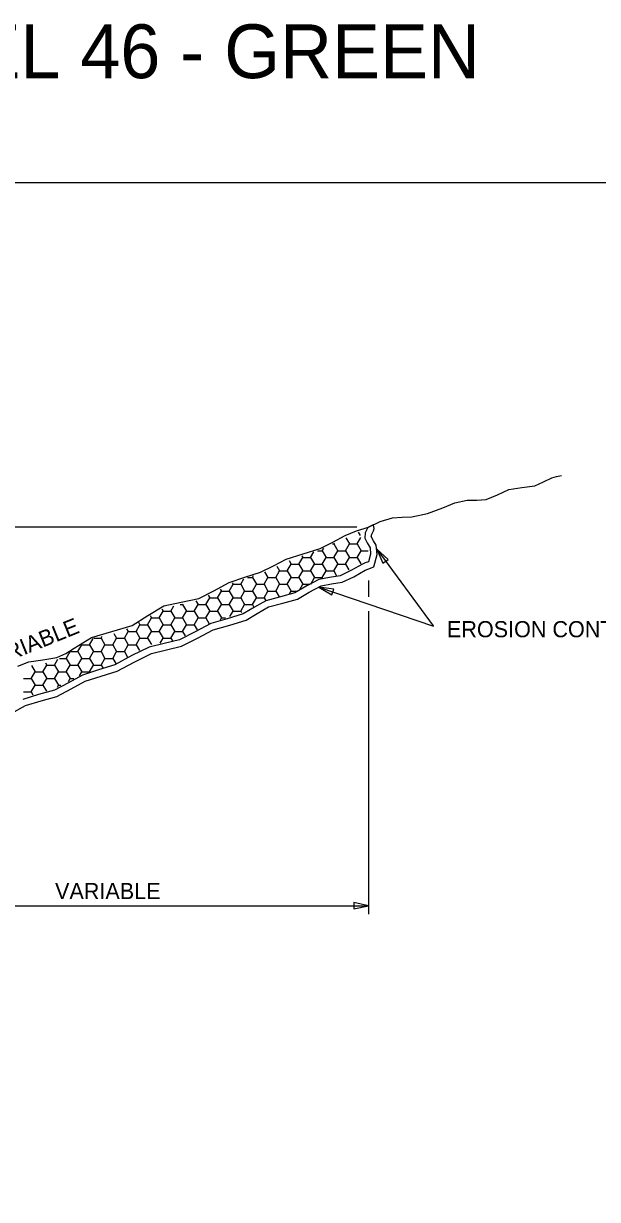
# Model space of a CAD drawing. Extents: x -439.1 to -407.9, y -458.1 to -436.2.
# Drawn here: x -424.75 to -419.41, y -447.12 to -436.2 of the extents above; entities that cross this region are included whole.
import ezdxf

# ---------------------------------------------------------------- set-up
doc = ezdxf.new("R2010")
doc.units = 0
for name, color, linetype in [('Default', 7, 'Continuous'), ('Draft_Named_Boundary', 7, 'Continuous'), ('Level 46', 7, 'Continuous')]:
    doc.layers.add(name, color=color, linetype=linetype)

msp = doc.modelspace()

# ---------------------------------------------------------------- linework, layer by layer
at = {"layer": 'Default'}
for p, q in [((-421.646, -440.877), (-427.407, -440.877)), ((-421.537, -440.877), (-421.544, -440.879)), ((-421.493, -440.855), (-421.537, -440.877)), ((-421.749, -440.976), (-421.715, -441.033)), ((-421.643, -441.033), (-421.608, -440.973)), ((-421.635, -440.923), (-421.616, -440.955)), ((-422.076, -441.158), (-422.047, -441.107)), ((-422.012, -441.096), (-421.968, -441.096)), ((-421.968, -441.096), (-421.954, -441.071)), ((-421.968, -441.096), (-421.932, -441.158)), ((-421.873, -441.033), (-421.86, -441.033)), ((-421.86, -441.033), (-421.855, -441.025)), ((-421.86, -441.033), (-421.824, -441.096)), ((-421.86, -441.158), (-421.824, -441.096)), ((-421.824, -441.096), (-421.752, -441.096)), ((-421.752, -441.096), (-421.715, -441.033)), ((-421.752, -441.096), (-421.715, -441.158)), ((-421.715, -441.033), (-421.643, -441.033)), ((-421.643, -441.033), (-421.607, -441.096)), ((-421.643, -441.158), (-421.607, -441.096)), ((-421.607, -441.096), (-421.541, -441.096)), ((-421.461, -441.081), (-420.937, -441.794)), ((-422.293, -441.283), (-422.257, -441.221)), ((-422.277, -441.186), (-422.257, -441.221)), ((-422.257, -441.221), (-422.185, -441.221)), ((-422.185, -441.221), (-422.148, -441.158)), ((-422.185, -441.221), (-422.148, -441.283)), ((-422.157, -441.144), (-422.148, -441.158)), ((-422.148, -441.158), (-422.076, -441.158)), ((-422.076, -441.158), (-422.04, -441.221)), ((-422.076, -441.283), (-422.04, -441.221)), ((-422.04, -441.221), (-421.968, -441.221)), ((-421.968, -441.221), (-421.932, -441.158)), ((-421.968, -441.221), (-421.932, -441.283)), ((-421.932, -441.158), (-421.86, -441.158)), ((-421.86, -441.158), (-421.824, -441.221)), ((-421.86, -441.283), (-421.824, -441.221)), ((-421.824, -441.221), (-421.752, -441.221)), ((-421.752, -441.221), (-421.715, -441.158)), ((-421.752, -441.221), (-421.72, -441.275)), ((-421.715, -441.158), (-421.643, -441.158)), ((-421.643, -441.158), (-421.608, -441.219)), ((-422.618, -441.346), (-422.606, -441.326)), ((-422.504, -441.292), (-422.473, -441.346)), ((-422.401, -441.346), (-422.365, -441.283)), ((-422.39, -441.24), (-422.365, -441.283)), ((-422.365, -441.283), (-422.293, -441.283)), ((-422.293, -441.283), (-422.257, -441.346)), ((-422.185, -441.346), (-422.148, -441.283)), ((-422.148, -441.283), (-422.076, -441.283)), ((-422.076, -441.283), (-422.04, -441.346)), ((-421.968, -441.346), (-421.932, -441.283)), ((-421.932, -441.283), (-421.86, -441.283)), ((-421.86, -441.283), (-421.834, -441.328)), ((-422.834, -441.471), (-422.798, -441.408)), ((-422.806, -441.394), (-422.798, -441.408)), ((-422.798, -441.408), (-422.726, -441.408)), ((-422.726, -441.408), (-422.696, -441.356)), ((-422.726, -441.408), (-422.69, -441.471)), ((-422.664, -441.346), (-422.618, -441.346)), ((-422.618, -441.346), (-422.581, -441.408)), ((-422.618, -441.471), (-422.581, -441.408)), ((-422.581, -441.408), (-422.509, -441.408)), ((-422.509, -441.408), (-422.473, -441.346)), ((-422.509, -441.408), (-422.473, -441.471)), ((-422.473, -441.346), (-422.401, -441.346)), ((-422.401, -441.346), (-422.365, -441.408)), ((-422.401, -441.471), (-422.365, -441.408)), ((-422.365, -441.408), (-422.293, -441.408)), ((-422.293, -441.408), (-422.257, -441.346)), ((-422.293, -441.408), (-422.257, -441.471)), ((-422.257, -441.346), (-422.185, -441.346)), ((-422.185, -441.346), (-422.148, -441.408)), ((-422.177, -441.457), (-422.148, -441.408)), ((-422.148, -441.408), (-422.08, -441.408)), ((-422.075, -441.406), (-422.04, -441.346)), ((-422.04, -441.346), (-421.968, -441.346)), ((-422.001, -441.435), (-420.932, -441.798)), ((-421.968, -441.346), (-421.965, -441.35)), ((-421.537, -441.373), (-421.537, -441.524)), ((-423.051, -441.596), (-423.015, -441.533)), ((-423.028, -441.509), (-423.015, -441.533)), ((-423.015, -441.533), (-422.942, -441.533)), ((-422.942, -441.533), (-422.906, -441.471)), ((-422.942, -441.533), (-422.906, -441.596)), ((-422.917, -441.452), (-422.906, -441.471)), ((-422.906, -441.471), (-422.834, -441.471)), ((-422.834, -441.471), (-422.798, -441.533)), ((-422.834, -441.596), (-422.798, -441.533)), ((-422.798, -441.533), (-422.726, -441.533)), ((-422.726, -441.533), (-422.69, -441.471)), ((-422.726, -441.533), (-422.69, -441.596)), ((-422.69, -441.471), (-422.618, -441.471)), ((-422.618, -441.471), (-422.581, -441.533)), ((-422.618, -441.596), (-422.581, -441.533)), ((-422.581, -441.533), (-422.509, -441.533)), ((-422.509, -441.533), (-422.473, -441.471)), ((-422.509, -441.533), (-422.491, -441.564)), ((-422.473, -441.471), (-422.401, -441.471)), ((-422.401, -441.471), (-422.37, -441.525)), ((-422.271, -441.496), (-422.257, -441.471)), ((-422.257, -441.471), (-422.204, -441.471)), ((-423.484, -441.721), (-423.448, -441.658)), ((-423.46, -441.637), (-423.448, -441.658)), ((-423.448, -441.658), (-423.375, -441.658)), ((-423.375, -441.658), (-423.347, -441.609)), ((-423.375, -441.658), (-423.339, -441.721)), ((-423.29, -441.596), (-423.267, -441.596)), ((-423.267, -441.596), (-423.264, -441.59)), ((-423.267, -441.596), (-423.231, -441.658)), ((-423.267, -441.721), (-423.231, -441.658)), ((-423.231, -441.658), (-423.159, -441.658)), ((-423.159, -441.658), (-423.123, -441.596)), ((-423.159, -441.658), (-423.123, -441.721)), ((-423.143, -441.561), (-423.123, -441.596)), ((-423.123, -441.596), (-423.051, -441.596)), ((-423.051, -441.596), (-423.015, -441.658)), ((-423.051, -441.721), (-423.015, -441.658)), ((-423.015, -441.658), (-422.942, -441.658)), ((-422.942, -441.658), (-422.906, -441.596)), ((-422.942, -441.658), (-422.906, -441.721)), ((-422.906, -441.596), (-422.834, -441.596)), ((-422.834, -441.596), (-422.798, -441.658)), ((-422.826, -441.707), (-422.798, -441.658)), ((-422.798, -441.658), (-422.726, -441.658)), ((-422.726, -441.658), (-422.69, -441.596)), ((-422.726, -441.658), (-422.718, -441.671)), ((-422.69, -441.596), (-422.618, -441.596)), ((-422.618, -441.596), (-422.604, -441.619)), ((-421.537, -441.657), (-421.537, -444.473)), ((-423.678, -441.76), (-423.664, -441.783)), ((-423.592, -441.783), (-423.556, -441.721)), ((-423.569, -441.698), (-423.556, -441.721)), ((-423.556, -441.721), (-423.484, -441.721)), ((-423.484, -441.721), (-423.448, -441.783)), ((-423.375, -441.783), (-423.339, -441.721)), ((-423.339, -441.721), (-423.267, -441.721)), ((-423.267, -441.721), (-423.231, -441.783)), ((-423.159, -441.783), (-423.123, -441.721)), ((-423.123, -441.721), (-423.051, -441.721)), ((-423.051, -441.721), (-423.019, -441.776)), ((-422.915, -441.737), (-422.906, -441.721)), ((-422.906, -441.721), (-422.868, -441.721)), ((-423.905, -441.866), (-423.881, -441.908)), ((-423.808, -441.908), (-423.772, -441.846)), ((-423.787, -441.821), (-423.772, -441.846)), ((-423.772, -441.846), (-423.7, -441.846)), ((-423.7, -441.846), (-423.664, -441.783)), ((-423.7, -441.846), (-423.664, -441.908)), ((-423.664, -441.783), (-423.592, -441.783)), ((-423.592, -441.783), (-423.556, -441.846)), ((-423.592, -441.908), (-423.556, -441.846)), ((-423.556, -441.846), (-423.484, -441.846)), ((-423.484, -441.846), (-423.448, -441.783)), ((-423.484, -441.846), (-423.448, -441.908)), ((-423.448, -441.783), (-423.375, -441.783)), ((-423.375, -441.783), (-423.339, -441.846)), ((-423.375, -441.908), (-423.339, -441.846)), ((-423.339, -441.846), (-423.267, -441.846)), ((-423.267, -441.846), (-423.231, -441.783)), ((-423.267, -441.846), (-423.244, -441.887)), ((-423.231, -441.783), (-423.159, -441.783)), ((-423.159, -441.783), (-423.131, -441.831)), ((-424.241, -442.033), (-424.205, -441.971)), ((-424.208, -441.967), (-424.205, -441.971)), ((-424.205, -441.971), (-424.133, -441.971)), ((-424.133, -441.971), (-424.098, -441.91)), ((-424.133, -441.971), (-424.097, -442.033)), ((-424.091, -441.908), (-424.025, -441.908)), ((-424.025, -441.908), (-424.015, -441.891)), ((-424.025, -441.908), (-423.989, -441.971)), ((-424.025, -442.033), (-423.989, -441.971)), ((-423.989, -441.971), (-423.917, -441.971)), ((-423.917, -441.971), (-423.881, -441.908)), ((-423.917, -441.971), (-423.881, -442.033)), ((-423.881, -441.908), (-423.808, -441.908)), ((-423.808, -441.908), (-423.772, -441.971)), ((-423.808, -442.033), (-423.772, -441.971)), ((-423.772, -441.971), (-423.7, -441.971)), ((-423.7, -441.971), (-423.664, -441.908)), ((-423.7, -441.971), (-423.669, -442.024)), ((-423.664, -441.908), (-423.592, -441.908)), ((-423.592, -441.908), (-423.557, -441.968)), ((-423.474, -441.954), (-423.448, -441.908)), ((-423.448, -441.908), (-423.375, -441.908)), ((-423.375, -441.908), (-423.361, -441.934)), ((-424.412, -442.096), (-424.35, -442.096)), ((-424.35, -442.096), (-424.314, -442.033)), ((-424.35, -442.096), (-424.314, -442.158)), ((-424.313, -442.033), (-424.241, -442.033)), ((-424.241, -442.033), (-424.205, -442.096)), ((-424.241, -442.158), (-424.205, -442.096)), ((-424.205, -442.096), (-424.133, -442.096)), ((-424.133, -442.096), (-424.097, -442.033)), ((-424.133, -442.096), (-424.097, -442.158)), ((-424.097, -442.033), (-424.025, -442.033)), ((-424.025, -442.033), (-423.989, -442.096)), ((-424.025, -442.158), (-423.989, -442.096)), ((-423.989, -442.096), (-423.917, -442.096)), ((-423.917, -442.096), (-423.881, -442.033)), ((-423.917, -442.096), (-423.888, -442.145)), ((-423.881, -442.033), (-423.808, -442.033)), ((-423.808, -442.033), (-423.779, -442.085)), ((-424.672, -442.162), (-424.638, -442.221)), ((-424.566, -442.221), (-424.53, -442.158)), ((-424.542, -442.137), (-424.53, -442.158)), ((-424.53, -442.158), (-424.458, -442.158)), ((-424.458, -442.158), (-424.427, -442.105)), ((-424.458, -442.158), (-424.422, -442.221)), ((-424.35, -442.221), (-424.314, -442.158)), ((-424.314, -442.158), (-424.241, -442.158)), ((-424.241, -442.158), (-424.205, -442.221)), ((-424.133, -442.22), (-424.097, -442.158)), ((-424.097, -442.158), (-424.025, -442.158)), ((-424.025, -442.158), (-424.009, -442.185)), ((-424.747, -442.283), (-424.674, -442.283)), ((-424.674, -442.283), (-424.638, -442.221)), ((-424.674, -442.283), (-424.638, -442.346)), ((-424.638, -442.221), (-424.566, -442.221)), ((-424.566, -442.221), (-424.53, -442.283)), ((-424.566, -442.346), (-424.53, -442.283)), ((-424.53, -442.283), (-424.458, -442.283)), ((-424.458, -442.283), (-424.422, -442.221)), ((-424.458, -442.283), (-424.422, -442.346)), ((-424.422, -442.221), (-424.35, -442.221)), ((-424.35, -442.221), (-424.314, -442.283)), ((-424.329, -442.31), (-424.314, -442.283)), ((-424.314, -442.283), (-424.277, -442.283)), ((-424.226, -442.257), (-424.205, -442.221)), ((-424.205, -442.221), (-424.134, -442.221)), ((-424.747, -442.408), (-424.674, -442.408)), ((-424.674, -442.408), (-424.638, -442.346)), ((-424.674, -442.408), (-424.659, -442.434)), ((-424.638, -442.346), (-424.566, -442.346)), ((-424.566, -442.346), (-424.534, -442.402)), ((-424.431, -442.363), (-424.422, -442.346)), ((-424.422, -442.346), (-424.399, -442.346)), ((-426.224, -444.395), (-421.537, -444.395))]:
    msp.add_line(p, q, dxfattribs=at)
for points in [[(-421.537, -440.877), (-421.429, -440.823), (-421.314, -440.791), (-421.224, -440.784), (-421.134, -440.78), (-420.988, -440.75), (-420.847, -440.697), (-420.736, -440.652), (-420.621, -440.626), (-420.531, -440.626), (-420.442, -440.62), (-420.338, -440.576), (-420.234, -440.526), (-420.112, -440.509), (-419.99, -440.492), (-419.911, -440.456), (-419.832, -440.418), (-419.788, -440.405), (-419.742, -440.396)], [(-424.8, -442.169), (-424.697, -442.127), (-424.567, -442.109), (-424.438, -442.088), (-424.354, -442.051), (-424.275, -442.001), (-424.114, -441.901), (-423.925, -441.847), (-423.737, -441.792), (-423.59, -441.698), (-423.441, -441.609), (-423.28, -441.573), (-423.117, -441.54), (-422.975, -441.468), (-422.835, -441.39), (-422.688, -441.342), (-422.541, -441.296), (-422.421, -441.235), (-422.302, -441.174), (-422.145, -441.124), (-421.988, -441.075), (-421.871, -441.016), (-421.755, -440.955), (-421.648, -440.911), (-421.537, -440.877)], [(-421.544, -440.879), (-421.569, -440.93), (-421.573, -440.978), (-421.55, -441.023), (-421.523, -441.068), (-421.519, -441.129), (-421.539, -441.198)], [(-421.491, -440.912), (-421.486, -440.89), (-421.487, -440.873), (-421.493, -440.855)], [(-421.488, -441.245), (-421.456, -441.13), (-421.465, -441.045), (-421.49, -441.005), (-421.512, -440.965), (-421.507, -440.942), (-421.491, -440.912)], [(-421.539, -441.198), (-421.568, -441.209), (-421.595, -441.221), (-421.697, -441.278), (-421.8, -441.328), (-421.9, -441.346), (-421.999, -441.364), (-422.111, -441.423), (-422.222, -441.488), (-422.357, -441.525), (-422.493, -441.561), (-422.598, -441.621), (-422.702, -441.683), (-422.852, -441.73), (-423.004, -441.772), (-423.151, -441.849), (-423.297, -441.924), (-423.437, -441.959), (-423.577, -441.992), (-423.738, -442.071), (-423.898, -442.156), (-424.048, -442.203), (-424.197, -442.251), (-424.327, -442.322), (-424.459, -442.391), (-424.606, -442.433), (-424.753, -442.477)], [(-424.86, -442.607), (-424.729, -442.534), (-424.583, -442.491), (-424.435, -442.449), (-424.303, -442.38), (-424.172, -442.308), (-424.023, -442.26), (-423.874, -442.214), (-423.716, -442.13), (-423.557, -442.051), (-423.416, -442.018), (-423.276, -441.983), (-423.129, -441.907), (-422.981, -441.83), (-422.827, -441.787), (-422.676, -441.74), (-422.573, -441.678), (-422.469, -441.618), (-422.333, -441.582), (-422.197, -441.545), (-422.089, -441.481), (-421.979, -441.423), (-421.881, -441.405), (-421.782, -441.388), (-421.674, -441.337), (-421.569, -441.277), (-421.544, -441.267), (-421.488, -441.245)]]:
    msp.add_lwpolyline(points, dxfattribs=at)
for points in [[(-421.356, -441.176), (-421.461, -441.081), (-421.403, -441.21)], [(-421.356, -441.176), (-421.461, -441.081), (-421.403, -441.21)], [(-421.861, -441.452), (-422.001, -441.435), (-421.879, -441.506)], [(-421.861, -441.452), (-422.001, -441.435), (-421.879, -441.506)], [(-421.675, -444.424), (-421.537, -444.395), (-421.675, -444.366)]]:
    msp.add_lwpolyline(points, close=True, dxfattribs=at)
at = {"layer": 'Draft_Named_Boundary'}
msp.add_lwpolyline([(-439.109, -458.051), (-407.859, -458.051), (-407.859, -437.676), (-439.109, -437.676)], close=True, dxfattribs=at)

# ---------------------------------------------------------------- texts
at = {"layer": 'Default'}
msp.add_text('VARIABLE', height=0.15, rotation=22, dxfattribs=at).set_placement((-425.125, -442.222))
for s, p in [('EROSION CONTROL GEOTEXTILE', (-420.808, -441.9)), ('VARIABLE', (-424.453, -444.333))]:
    msp.add_text(s, height=0.15, dxfattribs=at).set_placement(p)
at = {"layer": 'Level 46'}
msp.add_text('METRIC - LEVEL 46 - GREEN', height=0.5, dxfattribs=at).set_placement((-429.642, -436.705))

doc.saveas('drawing.dxf')
